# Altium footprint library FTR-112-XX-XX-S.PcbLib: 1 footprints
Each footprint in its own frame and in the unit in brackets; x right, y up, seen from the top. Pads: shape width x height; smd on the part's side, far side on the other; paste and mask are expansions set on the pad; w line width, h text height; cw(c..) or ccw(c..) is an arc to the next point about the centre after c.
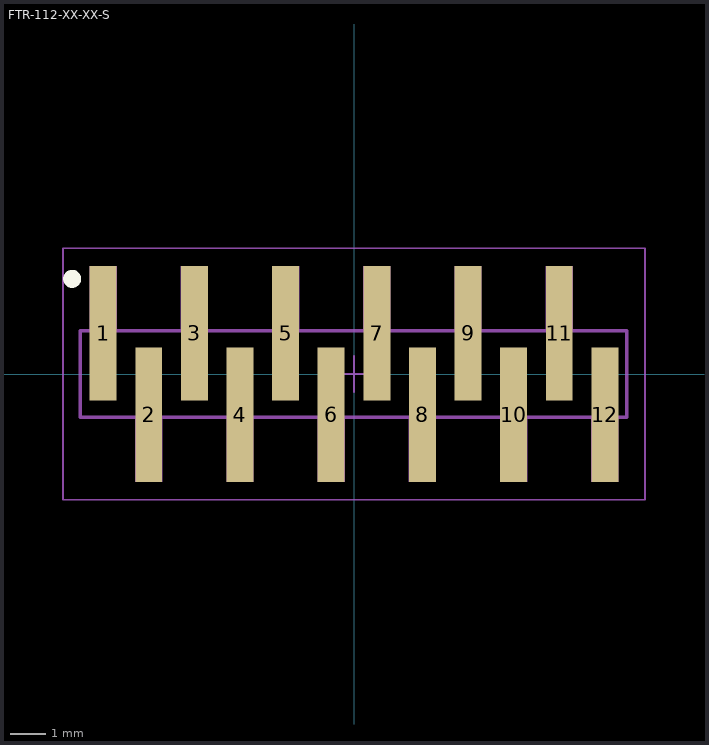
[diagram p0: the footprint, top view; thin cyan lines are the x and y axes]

## FTR-112-XX-XX-S [mm] "1.27mm pitch, 12 pin, micro terminal strip; single row"
height 9.65
pads (12):
  rect 0.75x3.75 smd mask+0: 1(-6.985,1.13) 2(-5.715,-1.13) 3(-4.445,1.13) 4(-3.175,-1.13) 5(-1.905,1.13) 6(-0.635,-1.13) 7(0.635,1.13) 8(1.905,-1.13) 9(3.175,1.13) 10(4.445,-1.13) 11(5.715,1.13) 12(6.985,-1.13)
Top Overlay:
  circle w0.25: c-7.85,2.65 r0.125
Mechanical 12:
  lines w0.001: -7.62,-1.2 7.6,-1.2 7.6,1.2 -7.62,1.2 -7.62,-1.2
Mechanical 13:
  region: -7.36,1.2 -6.61,1.2 -6.61,3 -7.36,3
  region: -4.82,1.2 -4.07,1.2 -4.07,3 -4.82,3
  region: -2.28,1.2 -1.53,1.2 -1.53,3 -2.28,3
  region: 0.26,1.2 1.01,1.2 1.01,3 0.26,3
  region: 2.8,1.2 3.55,1.2 3.55,3 2.8,3
  region: 5.34,1.2 6.09,1.2 6.09,3 5.34,3
  region: 6.61,-3 7.36,-3 7.36,-1.2 6.61,-1.2
  region: 4.07,-3 4.82,-3 4.82,-1.2 4.07,-1.2
  region: 1.53,-3 2.28,-3 2.28,-1.2 1.53,-1.2
  region: -1.01,-3 -0.26,-3 -0.26,-1.2 -1.01,-1.2
  region: -3.55,-3 -2.8,-3 -2.8,-1.2 -3.55,-1.2
  region: -6.09,-3 -5.34,-3 -5.34,-1.2 -6.09,-1.2
  lines w0.1: -7.62,-1.2 7.6,-1.2 7.6,1.2 -7.62,1.2 -7.62,-1.2
  text ".Designator" at 0.254,0.254 h1.52
Mechanical 15:
  lines w0.05: -0.5,0 0.5,0 ; 0,-0.5 0,0.5 ; -8.1,-3.5 8.1,-3.5 8.1,3.5 -8.1,3.5 -8.1,-3.5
